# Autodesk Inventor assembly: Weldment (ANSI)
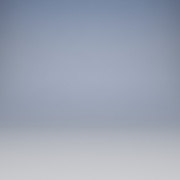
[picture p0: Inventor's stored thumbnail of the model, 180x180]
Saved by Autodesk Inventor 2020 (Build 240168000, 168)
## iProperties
Length Units: 11272
Angle Units: 11286
Time Units: 11279
Mass Units: 11290
Length Display Precision: 3
Angle Display Precision: 2
Part Number: Weldment (ANSI)
Document SubType Name: Weldment
Created: 2002-06
Designer: smithga
Created: 2002-08
Designer: F.Stasiak
Weld Material: Welded Aluminum-6061
Manager: www.cadconsulting.pl
Company: Fabian Stasiak CAD Consulting
Control State: 0
Master: False
Shininess: 64.0
Angle Units: 11279
Time Units: 11290
Mass Units: 11286
Compacted: True
Density: 0.0
Volumn: 0.0
Area: 0.0
PropertySet Name: Model Information
Author: F.Stasiak
Subject: Zbiór ćwiczeń. Autodesk Inventor 2020. Kurs podstawowy
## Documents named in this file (1)
- M:\AUTOBUILD\M24_168_RTM\Application\App\Templates\en-US\English\Weldment (ANSI).iam
